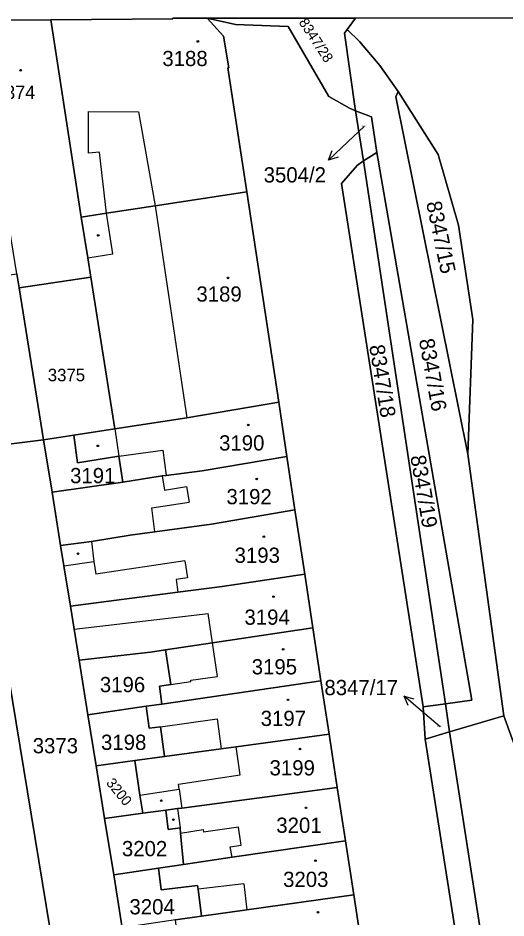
# Model space of a CAD drawing. Extents: x -596233 to -595156, y -1161235 to -1159375.
# Drawn here: x -595437.3 to -595382.9, y -1161139.4 to -1161038.9 of the extents above; entities that cross this region are included whole.
import ezdxf

# ---------------------------------------------------------------- set-up
doc = ezdxf.new("R2010")
doc.units = 0
for name, color, linetype in [('KN_CAR_KR', 7, 'Continuous'), ('KN_KULTURY', 7, 'Continuous'), ('KN_PARC_CIS_POM', 7, 'Continuous'), ('KN_PARC_CIS_POZ', 7, 'Continuous'), ('KN_PARC_CIS_STAV', 7, 'Continuous'), ('KN_PARC_PLOCHA', 7, 'Continuous'), ('PARC_C_SIPKA', 7, 'Continuous'), ('parcely_l', 7, 'Continuous')]:
    doc.layers.add(name, color=color, linetype=linetype)

msp = doc.modelspace()

# ---------------------------------------------------------------- linework, layer by layer
at = {"layer": 'KN_CAR_KR'}
for points in [[(-595429.46, -1161053.99), (-595429.43, -1161049.34)], [(-595429.43, -1161049.34), (-595423.87, -1161049.37)], [(-595423.87, -1161049.37), (-595422, -1161059.88)], [(-595428.21, -1161053.88), (-595429.46, -1161053.99)], [(-595427.42, -1161060.71), (-595428.21, -1161053.88)], [(-595422, -1161059.88), (-595418.48, -1161083.54)], [(-595426.73, -1161065.23), (-595427.42, -1161060.71)], [(-595429.53, -1161065.68), (-595426.73, -1161065.23)], [(-595426.49, -1161084.77), (-595426.05, -1161087.84)], [(-595426.05, -1161087.84), (-595421.17, -1161087.17)], [(-595421.17, -1161087.17), (-595420.79, -1161089.97)], [(-595421.24, -1161090.02), (-595420.98, -1161091.62)], [(-595420.98, -1161091.62), (-595418.5, -1161091.22)], [(-595418.5, -1161091.22), (-595418.22, -1161092.95)], [(-595422.03, -1161096.26), (-595422.38, -1161093.59), (-595418.22, -1161092.95)], [(-595429.11, -1161097.33), (-595428.85, -1161099.59)], [(-595432.18, -1161100.08), (-595428.85, -1161099.59)], [(-595428.85, -1161099.59), (-595428.64, -1161100.99)], [(-595418.68, -1161099.52), (-595428.64, -1161100.99)], [(-595418.68, -1161099.52), (-595418.4, -1161101.4)], [(-595418.4, -1161101.4), (-595419.67, -1161101.58)], [(-595419.67, -1161101.58), (-595419.46, -1161103.01)], [(-595431.04, -1161107.15), (-595416.1, -1161105.38)], [(-595415.61, -1161108.67), (-595416.1, -1161105.38)], [(-595415.07, -1161112.41), (-595415.61, -1161108.67)], [(-595420.26, -1161113.32), (-595418.01, -1161112.99)], [(-595418.03, -1161112.84), (-595415.07, -1161112.41)], [(-595418.01, -1161112.99), (-595418.03, -1161112.84)], [(-595421.43, -1161118.03), (-595415.09, -1161117.15)], [(-595415.09, -1161117.15), (-595414.63, -1161120.49)], [(-595412.51, -1161123.39), (-595412.99, -1161120.27)], [(-595419.42, -1161124.45), (-595412.51, -1161123.39)], [(-595423.7, -1161125.66), (-595419.34, -1161124.99)], [(-595419.34, -1161124.99), (-595419.42, -1161124.45)], [(-595419.34, -1161124.99), (-595419.03, -1161127.11)], [(-595419.52, -1161127.17), (-595419.23, -1161129.3)], [(-595412.71, -1161129.23), (-595416.63, -1161129.78)], [(-595412.43, -1161131.23), (-595412.71, -1161129.23)], [(-595419.17, -1161129.9), (-595416.64, -1161129.48)], [(-595416.64, -1161129.48), (-595416.63, -1161129.78)], [(-595413.63, -1161131.44), (-595412.43, -1161131.23)], [(-595413.43, -1161132.58), (-595413.63, -1161131.44)], [(-595412.12, -1161135.57), (-595417.22, -1161136.17)], [(-595412.12, -1161135.57), (-595411.78, -1161138.46)]]:
    msp.add_lwpolyline(points, dxfattribs=at)
at = {"layer": 'KN_KULTURY'}
for centre, radius in [((-595417.24, -1161041.53), 0.09), ((-595417.24, -1161041.53), 0.0398), ((-595437, -1161044.74), 0.09), ((-595437, -1161044.74), 0.0398), ((-595428.36, -1161063.18), 0.09), ((-595428.36, -1161063.18), 0.0398), ((-595413.89, -1161067.92), 0.09), ((-595413.89, -1161067.92), 0.0398), ((-595411.62, -1161084.34), 0.09), ((-595411.62, -1161084.34), 0.0398), ((-595428.4, -1161086.67), 0.09), ((-595428.4, -1161086.67), 0.0398), ((-595410.68, -1161090.37), 0.09), ((-595410.68, -1161090.37), 0.0398), ((-595409.88, -1161096.8), 0.09), ((-595409.88, -1161096.8), 0.0398), ((-595430.61, -1161098.71), 0.09), ((-595430.61, -1161098.71), 0.0398), ((-595408.81, -1161103.5), 0.09), ((-595408.81, -1161103.5), 0.0398), ((-595407.73, -1161109.39), 0.09), ((-595407.73, -1161109.39), 0.0398), ((-595407.2, -1161115.02), 0.09), ((-595407.2, -1161115.02), 0.0398), ((-595405.86, -1161120.51), 0.09), ((-595405.86, -1161120.51), 0.0398), ((-595421.31, -1161126.28), 0.09), ((-595421.31, -1161126.28), 0.0398), ((-595405.19, -1161127.08), 0.09), ((-595405.19, -1161127.08), 0.0398), ((-595419.97, -1161128.39), 0.09), ((-595419.97, -1161128.39), 0.0398), ((-595404.12, -1161132.97), 0.09), ((-595404.12, -1161132.97), 0.0398), ((-595403.85, -1161138.73), 0.09), ((-595403.85, -1161138.73), 0.0398)]:
    msp.add_circle(centre, radius, dxfattribs=at)
at = {"layer": 'KN_PARC_PLOCHA'}
for points in [[(-595363.91, -1161038.91), (-595399.65, -1161038.92), (-595416.22, -1161038.93), (-595420.04, -1161038.93), (-595420.04, -1161039), (-595433.64, -1161039.1), (-595443.38, -1161039.2), (-595450.27, -1161039.27), (-595458.03, -1161039.34), (-595467.87, -1161039.44), (-595478.92, -1161041.33), (-595478.92, -1161041.42), (-595484.41, -1161042.49), (-595489.91, -1161043.55)], [(-595398.95, -1161142.67), (-595399.85, -1161136.8), (-595400.77, -1161130.77), (-595401.69, -1161124.79), (-595402.61, -1161118.85), (-595403.52, -1161112.91), (-595404.41, -1161107), (-595405.32, -1161101), (-595406.41, -1161093.8), (-595407.32, -1161087.85), (-595408.23, -1161081.81), (-595411.79, -1161058.31), (-595413.89, -1161044.49), (-595413.79, -1161044.48), (-595414.37, -1161040.93), (-595416.22, -1161038.93), (-595413.05, -1161039.63), (-595407.18, -1161039.87), (-595402.64, -1161047.68), (-595400.34, -1161048.99), (-595399.66, -1161049.29), (-595398.78, -1161054.84), (-595399.46, -1161055.38), (-595401.22, -1161057.38), (-595392.12, -1161115.8), (-595391.89, -1161119.41), (-595383.72, -1161171.47)], [(-595377.05, -1161133.54), (-595383.13, -1161116.81), (-595387.12, -1161087.61), (-595386.58, -1161072.57), (-595388.18, -1161062.02), (-595390.45, -1161054.13), (-595394.89, -1161047.11), (-595396.96, -1161044.22), (-595399.23, -1161041.52), (-595400.6, -1161040.21), (-595399.65, -1161038.92), (-595363.91, -1161038.91)]]:
    msp.add_lwpolyline(points, dxfattribs=at)
for points in [[(-595430.25, -1161061.14), (-595429.53, -1161065.68), (-595429.19, -1161067.84), (-595437.18, -1161069.04), (-595437.43, -1161067.48), (-595438.65, -1161059.88), (-595439.39, -1161055.25), (-595441.91, -1161050.54), (-595442.25, -1161048.41), (-595443.38, -1161039.2), (-595433.64, -1161039.1), (-595431.06, -1161056.04)], [(-595411.79, -1161058.31), (-595422, -1161059.88), (-595427.42, -1161060.71), (-595430.25, -1161061.14), (-595431.06, -1161056.04), (-595433.64, -1161039.1), (-595420.04, -1161039), (-595420.04, -1161038.93), (-595416.22, -1161038.93), (-595414.37, -1161040.93), (-595413.79, -1161044.48), (-595413.89, -1161044.49)], [(-595400.6, -1161040.21), (-595400.88, -1161040.59), (-595399.66, -1161049.29), (-595400.34, -1161048.99), (-595402.64, -1161047.68), (-595407.18, -1161039.87), (-595413.05, -1161039.63), (-595416.22, -1161038.93), (-595399.65, -1161038.92)], [(-595394.89, -1161047.11), (-595395.16, -1161047.72), (-595387.12, -1161087.61), (-595383.13, -1161116.81), (-595389.18, -1161118.61), (-595389.63, -1161115.46), (-595386.67, -1161115.05), (-595397.28, -1161053.92), (-595397.86, -1161049.94), (-595399.66, -1161049.29), (-595400.88, -1161040.59), (-595400.6, -1161040.21), (-595399.23, -1161041.52), (-595396.96, -1161044.22)], [(-595387.12, -1161087.61), (-595395.16, -1161047.72), (-595394.89, -1161047.11), (-595390.45, -1161054.13), (-595388.18, -1161062.02), (-595386.58, -1161072.57)], [(-595397.28, -1161053.92), (-595398.78, -1161054.84), (-595399.66, -1161049.29), (-595397.86, -1161049.94)], [(-595438.65, -1161059.88), (-595441.71, -1161060.4), (-595440.5, -1161067.9), (-595437.43, -1161067.48), (-595437.18, -1161069.04), (-595434.45, -1161085.99), (-595442.55, -1161087), (-595443.36, -1161082.12), (-595444.7, -1161073.96), (-595443.12, -1161073.7), (-595444.26, -1161066.79), (-595445.84, -1161067.05), (-595446.78, -1161061.33), (-595443.46, -1161060.7), (-595444.95, -1161051.72), (-595441.91, -1161050.54), (-595439.39, -1161055.25)], [(-595389.63, -1161115.46), (-595392.12, -1161115.8), (-595401.22, -1161057.38), (-595399.46, -1161055.38), (-595398.78, -1161054.84)], [(-595389.63, -1161115.46), (-595398.78, -1161054.84), (-595397.28, -1161053.92), (-595386.67, -1161115.05)], [(-595408.23, -1161081.81), (-595418.48, -1161083.54), (-595426.49, -1161084.77), (-595429.19, -1161067.84), (-595429.53, -1161065.68), (-595430.25, -1161061.14), (-595427.42, -1161060.71), (-595422, -1161059.88), (-595411.79, -1161058.31)], [(-595426.49, -1161084.77), (-595431.08, -1161085.47), (-595434.45, -1161085.99), (-595437.18, -1161069.04), (-595429.19, -1161067.84)], [(-595407.32, -1161087.85), (-595416.77, -1161089.47), (-595420.79, -1161089.97), (-595421.24, -1161090.02), (-595421.45, -1161090.05), (-595425.63, -1161090.72), (-595426.05, -1161087.84), (-595430.66, -1161088.57), (-595431.08, -1161085.47), (-595426.49, -1161084.77), (-595418.48, -1161083.54), (-595408.23, -1161081.81)], [(-595433.51, -1161091.83), (-595432.55, -1161097.79), (-595432.18, -1161100.08), (-595431.46, -1161104.55), (-595431.04, -1161107.15), (-595430.49, -1161110.61), (-595429.51, -1161116.69), (-595428.59, -1161122.39), (-595427.65, -1161128.26), (-595426.63, -1161134.57), (-595425.68, -1161140.49), (-595424.8, -1161146.32), (-595423.86, -1161152.14), (-595431.62, -1161153.4), (-595442.55, -1161087), (-595434.45, -1161085.99)], [(-595425.63, -1161090.72), (-595433.51, -1161091.83), (-595434.45, -1161085.99), (-595431.08, -1161085.47), (-595430.66, -1161088.57), (-595426.05, -1161087.84)], [(-595431.62, -1161153.4), (-595440.14, -1161154.87), (-595450.32, -1161090.88), (-595450.6, -1161089.1), (-595442.55, -1161087)], [(-595406.41, -1161093.8), (-595415.73, -1161095.42), (-595422.03, -1161096.26), (-595424.8, -1161096.63), (-595429.11, -1161097.33), (-595432.55, -1161097.79), (-595433.51, -1161091.83), (-595425.63, -1161090.72), (-595421.45, -1161090.05), (-595421.24, -1161090.02), (-595420.79, -1161089.97), (-595416.77, -1161089.47), (-595407.32, -1161087.85)], [(-595405.32, -1161101), (-595414.52, -1161102.38), (-595419.46, -1161103.01), (-595423.74, -1161103.56), (-595431.46, -1161104.55), (-595432.18, -1161100.08), (-595432.55, -1161097.79), (-595429.11, -1161097.33), (-595424.8, -1161096.63), (-595422.03, -1161096.26), (-595415.73, -1161095.42), (-595406.41, -1161093.8)], [(-595404.41, -1161107), (-595415.61, -1161108.67), (-595420.86, -1161109.44), (-595422.54, -1161109.69), (-595430.49, -1161110.61), (-595431.04, -1161107.15), (-595431.46, -1161104.55), (-595423.74, -1161103.56), (-595419.46, -1161103.01), (-595414.52, -1161102.38), (-595405.32, -1161101)], [(-595403.52, -1161112.91), (-595421.25, -1161115.49), (-595421.54, -1161113.5), (-595420.26, -1161113.32), (-595420.86, -1161109.44), (-595415.61, -1161108.67), (-595404.41, -1161107)], [(-595421.25, -1161115.49), (-595423, -1161115.74), (-595429.51, -1161116.69), (-595430.49, -1161110.61), (-595422.54, -1161109.69), (-595420.86, -1161109.44), (-595420.26, -1161113.32), (-595421.54, -1161113.5)], [(-595402.61, -1161118.85), (-595412.99, -1161120.27), (-595414.63, -1161120.49), (-595420.97, -1161121.36), (-595421.43, -1161118.03), (-595422.66, -1161118.2), (-595423, -1161115.74), (-595421.25, -1161115.49), (-595403.52, -1161112.91)], [(-595420.97, -1161121.36), (-595424.29, -1161121.81), (-595428.59, -1161122.39), (-595429.51, -1161116.69), (-595423, -1161115.74), (-595422.66, -1161118.2), (-595421.43, -1161118.03)], [(-595389.18, -1161118.61), (-595391.89, -1161119.41), (-595392.12, -1161115.8), (-595389.63, -1161115.46)], [(-595371.26, -1161185.16), (-595377.43, -1161185.09), (-595379.06, -1161183.68), (-595389.18, -1161118.61), (-595383.13, -1161116.81), (-595377.05, -1161133.54), (-595369.73, -1161179.72), (-595369.64, -1161181.48), (-595370.09, -1161183.36), (-595370.98, -1161184.89)], [(-595401.69, -1161124.79), (-595419.03, -1161127.11), (-595419.52, -1161127.17), (-595420.83, -1161127.35), (-595423.39, -1161127.69), (-595423.7, -1161125.66), (-595424.29, -1161121.81), (-595420.97, -1161121.36), (-595414.63, -1161120.49), (-595412.99, -1161120.27), (-595402.61, -1161118.85)], [(-595371.26, -1161185.16), (-595372.21, -1161186.09), (-595373.72, -1161186.94), (-595375.42, -1161187.35), (-595377.23, -1161187.25), (-595378.79, -1161186.71), (-595380.41, -1161185.53), (-595381.58, -1161183.87), (-595382.14, -1161182.03), (-595383.72, -1161171.47), (-595391.89, -1161119.41), (-595389.18, -1161118.61), (-595379.06, -1161183.68), (-595377.43, -1161185.09)], [(-595423.39, -1161127.69), (-595427.65, -1161128.26), (-595428.59, -1161122.39), (-595424.29, -1161121.81), (-595423.7, -1161125.66)], [(-595400.77, -1161130.77), (-595413.43, -1161132.58), (-595418.83, -1161133.4), (-595419.17, -1161129.9), (-595419.23, -1161129.3), (-595420.54, -1161129.48), (-595420.83, -1161127.35), (-595419.52, -1161127.17), (-595419.03, -1161127.11), (-595401.69, -1161124.79)], [(-595418.83, -1161133.4), (-595421.64, -1161133.82), (-595426.63, -1161134.57), (-595427.65, -1161128.26), (-595423.39, -1161127.69), (-595420.83, -1161127.35), (-595420.54, -1161129.48), (-595419.23, -1161129.3), (-595419.17, -1161129.9)], [(-595399.85, -1161136.8), (-595411.78, -1161138.46), (-595416.83, -1161139.16), (-595417.22, -1161136.17), (-595417.28, -1161135.73), (-595421.35, -1161136.22), (-595421.64, -1161133.82), (-595418.83, -1161133.4), (-595413.43, -1161132.58), (-595400.77, -1161130.77)], [(-595416.83, -1161139.16), (-595419.74, -1161139.59), (-595425.68, -1161140.49), (-595426.63, -1161134.57), (-595421.64, -1161133.82), (-595421.35, -1161136.22), (-595417.28, -1161135.73), (-595417.22, -1161136.17)], [(-595398.95, -1161142.67), (-595411.83, -1161144.49), (-595412.72, -1161144.61), (-595417.04, -1161145.22), (-595417.33, -1161143.06), (-595419.28, -1161143.3), (-595419.74, -1161139.59), (-595416.83, -1161139.16), (-595411.78, -1161138.46), (-595399.85, -1161136.8)]]:
    msp.add_lwpolyline(points, close=True, dxfattribs=at)
at = {"layer": 'PARC_C_SIPKA'}
for points in [[(-595398.7, -1161051.04), (-595400.48, -1161052.71), (-595402.6638, -1161054.767)], [(-595401.593, -1161054.4453), (-595402.6638, -1161054.767), (-595402.2787, -1161053.7173)], [(-595393.7879, -1161115.6561), (-595394.2262, -1161114.6276), (-595393.1404, -1161114.894)], [(-595390.2, -1161118.02), (-595391.94, -1161116.57), (-595394.2262, -1161114.6276)]]:
    msp.add_lwpolyline(points, dxfattribs=at)
at = {"layer": 'parcely_l'}
for points in [[(-595433.64, -1161039.1), (-595443.38, -1161039.2)], [(-595433.64, -1161039.1), (-595420.04, -1161039), (-595420.04, -1161038.93), (-595416.22, -1161038.93)], [(-595430.25, -1161061.14), (-595431.06, -1161056.04), (-595433.64, -1161039.1)], [(-595399.65, -1161038.92), (-595416.22, -1161038.93)], [(-595416.22, -1161038.93), (-595414.37, -1161040.93), (-595413.79, -1161044.48), (-595413.89, -1161044.49), (-595411.79, -1161058.31)], [(-595399.66, -1161049.29), (-595400.34, -1161048.99), (-595402.64, -1161047.68), (-595407.18, -1161039.87), (-595413.05, -1161039.63), (-595416.22, -1161038.93)], [(-595399.65, -1161038.92), (-595400.6, -1161040.21)], [(-595363.91, -1161038.91), (-595399.65, -1161038.92)], [(-595399.66, -1161049.29), (-595400.88, -1161040.59), (-595400.6, -1161040.21)], [(-595400.6, -1161040.21), (-595399.23, -1161041.52), (-595396.96, -1161044.22), (-595394.89, -1161047.11)], [(-595394.89, -1161047.11), (-595395.16, -1161047.72), (-595387.12, -1161087.61)], [(-595394.89, -1161047.11), (-595390.45, -1161054.13), (-595388.18, -1161062.02), (-595386.58, -1161072.57), (-595387.12, -1161087.61)], [(-595397.28, -1161053.92), (-595397.86, -1161049.94), (-595399.66, -1161049.29)], [(-595399.66, -1161049.29), (-595398.78, -1161054.84)], [(-595392.12, -1161115.8), (-595401.22, -1161057.38), (-595399.46, -1161055.38), (-595398.78, -1161054.84)], [(-595398.78, -1161054.84), (-595397.28, -1161053.92)], [(-595398.78, -1161054.84), (-595389.63, -1161115.46)], [(-595389.63, -1161115.46), (-595386.67, -1161115.05), (-595397.28, -1161053.92)], [(-595430.25, -1161061.14), (-595427.42, -1161060.71), (-595422, -1161059.88), (-595411.79, -1161058.31)], [(-595411.79, -1161058.31), (-595408.23, -1161081.81)], [(-595429.19, -1161067.84), (-595429.53, -1161065.68), (-595430.25, -1161061.14)], [(-595437.43, -1161067.48), (-595437.18, -1161069.04)], [(-595437.18, -1161069.04), (-595429.19, -1161067.84)], [(-595426.49, -1161084.77), (-595429.19, -1161067.84)], [(-595434.45, -1161085.99), (-595437.18, -1161069.04)], [(-595408.23, -1161081.81), (-595418.48, -1161083.54), (-595426.49, -1161084.77)], [(-595408.23, -1161081.81), (-595407.32, -1161087.85)], [(-595426.49, -1161084.77), (-595431.08, -1161085.47)], [(-595442.55, -1161087), (-595434.45, -1161085.99)], [(-595431.08, -1161085.47), (-595434.45, -1161085.99)], [(-595434.45, -1161085.99), (-595433.51, -1161091.83)], [(-595425.63, -1161090.72), (-595426.05, -1161087.84), (-595430.66, -1161088.57), (-595431.08, -1161085.47)], [(-595431.62, -1161153.4), (-595442.55, -1161087)], [(-595407.32, -1161087.85), (-595416.77, -1161089.47), (-595420.79, -1161089.97), (-595421.24, -1161090.02), (-595421.45, -1161090.05), (-595425.63, -1161090.72)], [(-595406.41, -1161093.8), (-595407.32, -1161087.85)], [(-595387.12, -1161087.61), (-595383.13, -1161116.81)], [(-595425.63, -1161090.72), (-595433.51, -1161091.83)], [(-595433.51, -1161091.83), (-595432.55, -1161097.79)], [(-595432.55, -1161097.79), (-595429.11, -1161097.33), (-595424.8, -1161096.63), (-595422.03, -1161096.26), (-595415.73, -1161095.42), (-595406.41, -1161093.8)], [(-595406.41, -1161093.8), (-595405.32, -1161101)], [(-595431.46, -1161104.55), (-595432.18, -1161100.08), (-595432.55, -1161097.79)], [(-595405.32, -1161101), (-595414.52, -1161102.38), (-595419.46, -1161103.01), (-595423.74, -1161103.56), (-595431.46, -1161104.55)], [(-595404.41, -1161107), (-595405.32, -1161101)], [(-595431.46, -1161104.55), (-595431.04, -1161107.15), (-595430.49, -1161110.61)], [(-595420.86, -1161109.44), (-595415.61, -1161108.67), (-595404.41, -1161107)], [(-595403.52, -1161112.91), (-595404.41, -1161107)], [(-595430.49, -1161110.61), (-595422.54, -1161109.69), (-595420.86, -1161109.44)], [(-595420.86, -1161109.44), (-595420.26, -1161113.32), (-595421.54, -1161113.5), (-595421.25, -1161115.49)], [(-595430.49, -1161110.61), (-595429.51, -1161116.69)], [(-595403.52, -1161112.91), (-595421.25, -1161115.49)], [(-595402.61, -1161118.85), (-595403.52, -1161112.91)], [(-595423, -1161115.74), (-595429.51, -1161116.69)], [(-595421.25, -1161115.49), (-595423, -1161115.74)], [(-595423, -1161115.74), (-595422.66, -1161118.2), (-595421.43, -1161118.03), (-595420.97, -1161121.36)], [(-595392.12, -1161115.8), (-595389.63, -1161115.46)], [(-595391.89, -1161119.41), (-595392.12, -1161115.8)], [(-595389.18, -1161118.61), (-595389.63, -1161115.46)], [(-595429.51, -1161116.69), (-595428.59, -1161122.39)], [(-595383.13, -1161116.81), (-595389.18, -1161118.61)], [(-595383.13, -1161116.81), (-595377.05, -1161133.54), (-595369.73, -1161179.72), (-595369.64, -1161181.48), (-595370.09, -1161183.36), (-595370.98, -1161184.89), (-595371.26, -1161185.16)], [(-595420.97, -1161121.36), (-595414.63, -1161120.49), (-595412.99, -1161120.27), (-595402.61, -1161118.85)], [(-595401.69, -1161124.79), (-595402.61, -1161118.85)], [(-595389.18, -1161118.61), (-595391.89, -1161119.41)], [(-595371.26, -1161185.16), (-595377.43, -1161185.09), (-595379.06, -1161183.68), (-595389.18, -1161118.61)], [(-595391.89, -1161119.41), (-595383.72, -1161171.47), (-595382.14, -1161182.03)], [(-595428.59, -1161122.39), (-595424.29, -1161121.81)], [(-595424.29, -1161121.81), (-595420.97, -1161121.36)], [(-595424.29, -1161121.81), (-595423.7, -1161125.66), (-595423.39, -1161127.69)], [(-595428.59, -1161122.39), (-595427.65, -1161128.26)], [(-595401.69, -1161124.79), (-595419.03, -1161127.11), (-595419.52, -1161127.17), (-595420.83, -1161127.35)], [(-595400.77, -1161130.77), (-595401.69, -1161124.79)], [(-595427.65, -1161128.26), (-595423.39, -1161127.69)], [(-595423.39, -1161127.69), (-595420.83, -1161127.35)], [(-595420.83, -1161127.35), (-595420.54, -1161129.48), (-595419.23, -1161129.3), (-595419.17, -1161129.9), (-595418.83, -1161133.4)], [(-595426.63, -1161134.57), (-595427.65, -1161128.26)], [(-595418.83, -1161133.4), (-595413.43, -1161132.58), (-595400.77, -1161130.77)], [(-595400.77, -1161130.77), (-595399.85, -1161136.8)], [(-595421.64, -1161133.82), (-595426.63, -1161134.57)], [(-595418.83, -1161133.4), (-595421.64, -1161133.82)], [(-595416.83, -1161139.16), (-595417.22, -1161136.17), (-595417.28, -1161135.73), (-595421.35, -1161136.22), (-595421.64, -1161133.82)], [(-595426.63, -1161134.57), (-595425.68, -1161140.49)], [(-595416.83, -1161139.16), (-595411.78, -1161138.46), (-595399.85, -1161136.8)], [(-595399.85, -1161136.8), (-595398.95, -1161142.67)], [(-595419.74, -1161139.59), (-595416.83, -1161139.16)]]:
    msp.add_lwpolyline(points, dxfattribs=at)

# ---------------------------------------------------------------- texts
at = {"layer": 'KN_PARC_CIS_POM'}
for s, p in [('3504/2', (-595398.9833, -1161051.04)), ('8347/17', (-595390.5333, -1161118.02))]:
    msp.add_text(s, height=0.1, dxfattribs=at).set_placement(p)
at = {"layer": 'KN_PARC_CIS_POZ'}
for s, height, rotation, p in [('8347/28', 1.14, 303.203381, (-595406.0409, -1161039.3905)), ('8347/15', 1.7, 281.836087, (-595391.7923, -1161059.5339)), ('8347/16', 1.7, 280.31501, (-595392.5947, -1161074.845)), ('8347/18', 1.7, 279.203011, (-595398.1363, -1161075.5063)), ('8347/19', 1.7, 279.673506, (-595393.5522, -1161087.844)), ('3200', 1.14, 309.057776, (-595427.5369, -1161124.3271))]:
    msp.add_text(s, height=height, rotation=rotation, dxfattribs=at).set_placement(p)
for s, height, p in [('3504/2', 1.7, (-595409.9066, -1161057.27)), ('3375', 1.4, (-595433.9866, -1161079.46)), ('3191', 1.7, (-595431.4966, -1161090.84)), ('3196', 1.7, (-595428.1766, -1161114.17)), ('8347/17', 1.7, (-595403.1316, -1161114.5)), ('3198', 1.7, (-595428.0466, -1161120.61)), ('3373', 1.7, (-595435.6666, -1161120.99)), ('3202', 1.7, (-595425.7166, -1161132.48)), ('3204', 1.7, (-595424.8766, -1161138.97))]:
    msp.add_text(s, height=height, dxfattribs=at).set_placement(p)
at = {"layer": 'KN_PARC_CIS_STAV'}
for s, height, p in [('3188', 1.7, (-595421.2066, -1161044.28)), ('3374', 1.5, (-595439.85, -1161047.96)), ('3189', 1.7, (-595417.4066, -1161070.57)), ('3190', 1.7, (-595414.8766, -1161087.19)), ('3192', 1.7, (-595414.0566, -1161093.19)), ('3193', 1.7, (-595413.1466, -1161099.73)), ('3194', 1.7, (-595412.0466, -1161106.64)), ('3195', 1.7, (-595411.2366, -1161112.18)), ('3197', 1.7, (-595410.2366, -1161117.94)), ('3199', 1.7, (-595409.2466, -1161123.46)), ('3201', 1.7, (-595408.4966, -1161129.87)), ('3203', 1.7, (-595407.7366, -1161135.91))]:
    msp.add_text(s, height=height, dxfattribs=at).set_placement(p)

doc.saveas('drawing.dxf')
